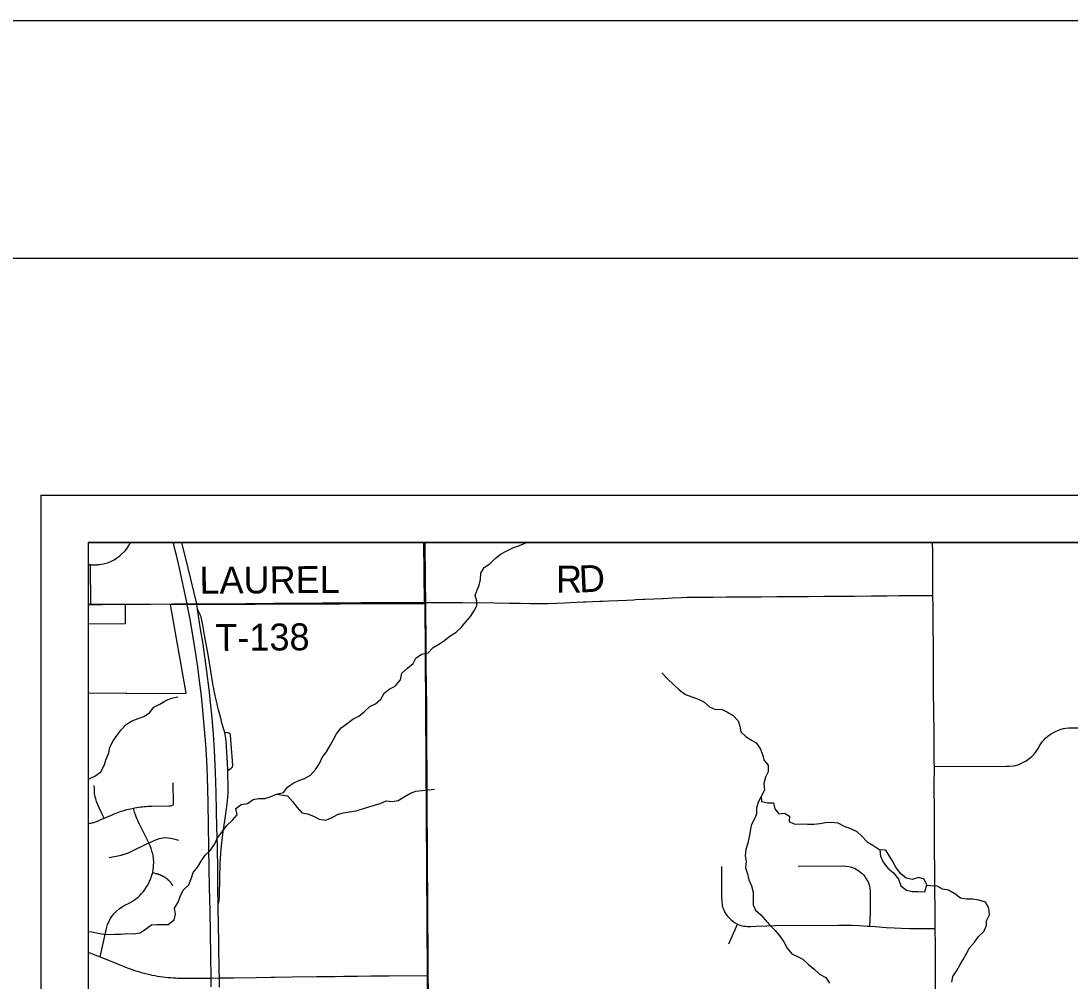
# Model space of a CAD drawing. Extents: x 0 to 34, y 0 to 22.
# Drawn here: x 1.958 to 4.171, y 19.975 to 22 of the extents above; entities that cross this region are included whole.
import ezdxf

# ---------------------------------------------------------------- set-up
doc = ezdxf.new("R2010")
doc.units = 0
for name, color, linetype in [('GM_X_City_Street', 7, 'Continuous'), ('GM_X_Corporation', 7, 'Continuous'), ('GM_X_County_Road', 7, 'Continuous'), ('GM_X_Interchange_Ramps', 7, 'Continuous'), ('GM_X_Interstate_Route', 7, 'Continuous'), ('GM_X_Minor_Lake', 7, 'Continuous'), ('GM_X_Minor_River', 7, 'Continuous'), ('GM_X_Township_Road', 7, 'Continuous'), ('GM_X_Township_Road_Text', 7, 'Continuous'), ('SH_Border', 7, 'Continuous'), ('SH_Cut_Line', 7, 'Continuous'), ('SH_Data', 7, 'Continuous')]:
    doc.layers.add(name, color=color, linetype=linetype)

msp = doc.modelspace()

# ---------------------------------------------------------------- linework, layer by layer
at = {"layer": 'GM_X_City_Street'}
for points in [[(2.1049, 20.8529), (2.1165, 20.8532), (2.118, 20.8533), (2.1195, 20.8534), (2.1209, 20.8535), (2.1242, 20.8539), (2.1315, 20.855), (2.1409, 20.8574), (2.1479, 20.8603), (2.1545, 20.8637), (2.1607, 20.8675), (2.1667, 20.8718), (2.1706, 20.8755), (2.1771, 20.8822), (2.1813, 20.8871), (2.1857, 20.8935), (2.1891, 20.9)], [(2.1058, 20.7696), (2.1049, 20.8529), (2.1, 20.8529)]]:
    msp.add_lwpolyline(points, dxfattribs=at)
at = {"layer": 'GM_X_Corporation'}
msp.add_lwpolyline([(7.991, 17.7727), (7.9901, 18.1613), (7.988, 19.001), (7.9884, 19.0254), (7.9898, 19.1149), (7.9901, 19.6615), (7.9904, 20.2824), (7.9906, 20.6512), (7.9922, 20.9), (2.1, 20.9), (2.1, 14.1)], dxfattribs=at)
for points in [[(2.8077, 20.9), (2.1, 20.9), (2.1, 20.77), (2.1778, 20.7703), (2.1782, 20.7286), (2.1, 20.7282), (2.1, 20.5821), (2.1799, 20.5828), (2.1799, 20.5819), (2.3067, 20.5825), (2.2736, 20.7693), (2.8091, 20.7716)], [(2.8099, 20.9), (2.1, 20.9), (2.1, 19.0167), (2.421, 19.0236), (2.4288, 19.0238), (2.4392, 19.024), (2.8247, 19.0323), (2.8158, 19.9868), (2.8107, 20.774)], [(7.9922, 20.9), (2.8099, 20.9), (2.8107, 20.774), (2.8158, 19.9868), (2.8247, 19.0323), (3.279, 19.0395), (3.3208, 19.0402), (3.8964, 19.0508), (4.1999, 19.0575), (4.5008, 19.0629), (4.7704, 19.0672), (4.9094, 19.0728), (5.4081, 19.0763), (6.7986, 19.0964), (7.9898, 19.1149), (7.9901, 19.6615), (7.9904, 20.2824), (7.9906, 20.6512)]]:
    msp.add_lwpolyline(points, close=True, dxfattribs=at)
at = {"layer": 'GM_X_County_Road'}
for points in [[(2.8123, 20.7736), (2.8116, 20.8163), (2.8114, 20.8343), (2.8107, 20.8878), (2.8106, 20.9)], [(2.8185, 19.9221), (2.8174, 19.9871), (2.8171, 20.0205), (2.8168, 20.0629), (2.8167, 20.0878), (2.8166, 20.1044), (2.8165, 20.1166), (2.8162, 20.1612), (2.8161, 20.1727), (2.8159, 20.1965), (2.8157, 20.2197), (2.8156, 20.231), (2.8157, 20.271), (2.8153, 20.3258), (2.8149, 20.3639), (2.8148, 20.4016), (2.8147, 20.4326), (2.8146, 20.4531), (2.8145, 20.4695), (2.8142, 20.5109), (2.8141, 20.5363), (2.814, 20.5513), (2.8136, 20.5994), (2.8132, 20.6382), (2.8129, 20.6853), (2.8128, 20.7144), (2.8125, 20.7374), (2.8125, 20.7518), (2.8123, 20.7736)], [(2.1, 20.0362), (2.1142, 20.0305), (2.1256, 20.0264), (2.1622, 20.0116), (2.1822, 20.0035), (2.1874, 20.0015), (2.1899, 20.0006), (2.1926, 19.9996), (2.1975, 19.9979), (2.1979, 19.9978), (2.2031, 19.9961), (2.2084, 19.9945), (2.2138, 19.993), (2.2141, 19.9929), (2.2191, 19.9916), (2.2245, 19.9902), (2.2299, 19.989), (2.2325, 19.9885), (2.2353, 19.9879), (2.2408, 19.9868), (2.2462, 19.9859), (2.2512, 19.9851), (2.2517, 19.985), (2.2572, 19.9843), (2.2627, 19.9836), (2.2682, 19.983), (2.2737, 19.9826), (2.2793, 19.9822), (2.283, 19.982), (2.2848, 19.9819), (2.2891, 19.9817), (2.2995, 19.9816), (2.33, 19.9812), (2.3594, 19.9817), (2.3769, 19.9819), (2.3882, 19.982)], [(2.3882, 19.982), (2.3954, 19.9821), (2.4073, 19.9822), (2.4548, 19.9829), (2.4853, 19.9833), (2.4928, 19.9834), (2.5299, 19.9839), (2.5824, 19.9846), (2.6106, 19.9849), (2.6203, 19.985), (2.6393, 19.9853), (2.6495, 19.9854), (2.6678, 19.9857), (2.6961, 19.986), (2.704, 19.9862), (2.7148, 19.9863), (2.7339, 19.9866), (2.8174, 19.9871)]]:
    msp.add_lwpolyline(points, dxfattribs=at)
at = {"layer": 'GM_X_Interchange_Ramps'}
for points in [[(2.3743, 20.135), (2.3757, 20.1409), (2.3765, 20.1455), (2.3771, 20.1572), (2.3784, 20.2242), (2.3804, 20.2539), (2.3843, 20.2851), (2.3891, 20.3178), (2.3923, 20.3433), (2.3944, 20.3621), (2.3952, 20.3754), (2.3956, 20.3917), (2.3947, 20.4089), (2.3943, 20.4196), (2.3937, 20.4345), (2.3907, 20.4821), (2.3903, 20.4871), (2.3898, 20.4912), (2.3891, 20.4949), (2.3882, 20.4992), (2.3862, 20.5057), (2.3835, 20.5149), (2.3814, 20.5222), (2.3802, 20.5268), (2.3776, 20.5373), (2.3751, 20.5472), (2.3736, 20.5531), (2.3718, 20.5601), (2.37, 20.5683), (2.368, 20.577), (2.3665, 20.5844), (2.3658, 20.5875), (2.3648, 20.5923), (2.3638, 20.5978), (2.363, 20.602), (2.3586, 20.629), (2.3528, 20.6638), (2.3457, 20.705), (2.3419, 20.7256), (2.3382, 20.7434), (2.3371, 20.7465), (2.3355, 20.7498), (2.3307, 20.7596)], [(2.3943, 20.4196), (2.4016, 20.4244), (2.4031, 20.4255), (2.4041, 20.4267), (2.4046, 20.4279), (2.4049, 20.4297), (2.4036, 20.4486), (2.4023, 20.4656), (2.4008, 20.4846), (2.4002, 20.4941), (2.4, 20.4954), (2.3995, 20.4966), (2.3986, 20.4974), (2.3977, 20.4979), (2.3965, 20.4983), (2.3945, 20.4985), (2.3882, 20.4992)]]:
    msp.add_lwpolyline(points, dxfattribs=at)
at = {"layer": 'GM_X_Interstate_Route'}
for points in [[(2.3088, 20.7697), (2.3086, 20.7707), (2.2912, 20.8525), (2.2883, 20.8646), (2.286, 20.8738), (2.2838, 20.883), (2.2806, 20.8959), (2.2795, 20.9)], [(2.329, 20.7708), (2.3108, 20.8461), (2.2974, 20.9)], [(2.3597, 19.9628), (2.3594, 19.9817), (2.357, 20.1241), (2.3562, 20.1722), (2.3553, 20.2126), (2.3544, 20.2567), (2.3539, 20.3031), (2.3532, 20.3522), (2.3514, 20.4059), (2.35, 20.4413), (2.3479, 20.4739), (2.3448, 20.5139), (2.3417, 20.5463), (2.3389, 20.5765), (2.335, 20.6082), (2.3311, 20.6377), (2.3245, 20.6828), (2.3152, 20.7382), (2.3088, 20.7697)], [(2.3773, 19.9621), (2.3769, 19.9819), (2.3763, 19.999), (2.3759, 20.0507), (2.3749, 20.0994), (2.3745, 20.1253), (2.3743, 20.135), (2.3737, 20.1693), (2.3732, 20.2102), (2.3728, 20.2568), (2.3713, 20.3002), (2.371, 20.3333), (2.37, 20.3729), (2.3689, 20.4151), (2.3665, 20.4623), (2.3643, 20.4961), (2.3613, 20.5298), (2.3583, 20.5629), (2.3552, 20.59), (2.3505, 20.6279), (2.3424, 20.6858), (2.3372, 20.7177), (2.3307, 20.7596), (2.329, 20.7708)]]:
    msp.add_lwpolyline(points, dxfattribs=at)
at = {"layer": 'GM_X_Minor_Lake'}
for points in [[(3.7698, 20.2527), (3.7708, 20.2386), (3.7767, 20.2258), (3.7863, 20.2131), (3.7982, 20.2034), (3.8091, 20.1899), (3.8142, 20.1764), (3.8257, 20.1671), (3.8379, 20.1643), (3.8508, 20.1641), (3.8644, 20.1636)], [(3.7699, 20.2523), (3.7708, 20.2386), (3.7767, 20.2258), (3.7863, 20.2131), (3.7982, 20.2034), (3.8091, 20.1899), (3.8142, 20.1764), (3.8257, 20.1671), (3.8379, 20.1643), (3.8508, 20.1641), (3.8644, 20.1636)], [(3.8644, 20.1636), (3.8687, 20.1781), (3.8635, 20.1905), (3.851, 20.1937), (3.8382, 20.1893), (3.8249, 20.1921), (3.813, 20.2022), (3.8037, 20.2153), (3.7974, 20.2277), (3.7904, 20.239), (3.7823, 20.2513), (3.7699, 20.2523)], [(3.8644, 20.1636), (3.8687, 20.1781), (3.8635, 20.1905), (3.851, 20.1937), (3.8382, 20.1893), (3.8249, 20.1921), (3.813, 20.2022), (3.8037, 20.2153), (3.7974, 20.2277), (3.7904, 20.239), (3.7823, 20.2513), (3.7701, 20.2523)]]:
    msp.add_lwpolyline(points, dxfattribs=at)
at = {"layer": 'GM_X_Minor_River'}
for points in [[(2.4971, 20.3693), (2.5121, 20.3729), (2.5206, 20.3845), (2.5326, 20.3923), (2.5442, 20.3982), (2.5566, 20.4026), (2.5686, 20.4096), (2.5798, 20.4216), (2.5882, 20.4338), (2.5933, 20.4465), (2.6026, 20.4588), (2.6107, 20.4718), (2.6176, 20.4844), (2.6238, 20.4967), (2.6334, 20.509), (2.6461, 20.5187), (2.6585, 20.5273), (2.6708, 20.534), (2.6824, 20.5433), (2.6943, 20.5545), (2.7063, 20.56), (2.7175, 20.5701), (2.7241, 20.5827), (2.7345, 20.5909), (2.7476, 20.5975), (2.7584, 20.6106), (2.7612, 20.6243), (2.7738, 20.6352), (2.7854, 20.6449), (2.7913, 20.6564), (2.8032, 20.6645), (2.8168, 20.6678), (2.8279, 20.6786), (2.8407, 20.6864), (2.8522, 20.6942), (2.8634, 20.7032), (2.8758, 20.711), (2.8866, 20.721), (2.8962, 20.7326), (2.9066, 20.7438), (2.9151, 20.7572), (2.9194, 20.7668), (2.9197, 20.7763), (2.9164, 20.7883), (2.92, 20.7979), (2.9247, 20.8101), (2.9272, 20.8223), (2.9284, 20.8352), (2.9354, 20.8475), (2.9474, 20.8549), (2.9585, 20.8665), (2.9697, 20.8754), (2.9828, 20.8829), (2.996, 20.8888), (3.0095, 20.8936), (3.0219, 20.8991), (3.0245, 20.9)], [(3.31, 20.6252), (3.3228, 20.6122), (3.3347, 20.601), (3.3462, 20.5894), (3.36, 20.5794), (3.373, 20.5747), (3.3851, 20.5704), (3.3985, 20.5641), (3.4104, 20.5534), (3.423, 20.5483), (3.4358, 20.5489), (3.4484, 20.5423), (3.4607, 20.5356), (3.4711, 20.5244), (3.4743, 20.5127), (3.4764, 20.5006), (3.4875, 20.4906), (3.499, 20.4836), (3.5086, 20.478), (3.5171, 20.4657), (3.5219, 20.4528), (3.5259, 20.4404), (3.534, 20.4303), (3.5339, 20.4166), (3.5288, 20.4051), (3.5252, 20.3918), (3.5262, 20.3782), (3.5193, 20.3644)], [(2.1, 20.4013), (2.102, 20.4018), (2.1143, 20.4077), (2.127, 20.4167), (2.134, 20.4297), (2.1383, 20.4434), (2.1437, 20.4564), (2.1458, 20.4686), (2.1528, 20.4816), (2.1609, 20.4939), (2.1694, 20.5054), (2.1805, 20.517), (2.1929, 20.5244), (2.2053, 20.5288), (2.2173, 20.5332), (2.2296, 20.541), (2.2385, 20.5526), (2.2513, 20.5592), (2.264, 20.5667), (2.276, 20.5718), (2.2892, 20.5747)], [(2.4971, 20.3693), (2.5202, 20.3662), (2.531, 20.3539), (2.5411, 20.3416), (2.5503, 20.3303), (2.5625, 20.3279), (2.5751, 20.3232), (2.5873, 20.3166), (2.6002, 20.3145), (2.613, 20.3193), (2.6257, 20.3263), (2.6381, 20.3304), (2.6513, 20.3321), (2.6649, 20.3342), (2.6784, 20.3387), (2.6901, 20.3419), (2.7036, 20.3463), (2.7161, 20.3499), (2.7284, 20.3555), (2.7413, 20.3538), (2.7538, 20.3559), (2.7665, 20.3637), (2.7796, 20.3715), (2.7913, 20.3755), (2.8045, 20.3773), (2.8173, 20.3783), (2.8302, 20.38)], [(2.1, 20.0795), (2.1076, 20.079), (2.1209, 20.0765), (2.1327, 20.0745), (2.1425, 20.0735), (2.1558, 20.0741), (2.169, 20.0743), (2.1826, 20.0753), (2.1955, 20.0748), (2.2094, 20.0773), (2.2206, 20.0844), (2.2333, 20.0937), (2.2451, 20.0946), (2.2572, 20.0945), (2.2689, 20.0947), (2.2816, 20.1044), (2.2844, 20.1162), (2.2819, 20.1291), (2.2896, 20.1417), (2.294, 20.1536), (2.3005, 20.167), (2.3121, 20.1782), (2.3171, 20.1912), (2.3211, 20.2041), (2.3311, 20.2165), (2.338, 20.228), (2.3469, 20.241), (2.3577, 20.2514), (2.3669, 20.2649), (2.3727, 20.2771), (2.3823, 20.2898), (2.3927, 20.3037), (2.4042, 20.3145), (2.4142, 20.3257), (2.4117, 20.3393), (2.4226, 20.3478), (2.4361, 20.35), (2.4477, 20.3585), (2.4594, 20.3602), (2.4723, 20.3605), (2.4839, 20.3637), (2.4971, 20.3693)], [(3.5193, 20.3644), (3.5138, 20.3537), (3.5095, 20.3407), (3.5093, 20.327), (3.505, 20.3174), (3.4984, 20.304), (3.496, 20.2915), (3.4939, 20.2793), (3.4915, 20.266), (3.4868, 20.253), (3.4859, 20.2397), (3.4876, 20.2276), (3.4867, 20.2139), (3.4907, 20.2011), (3.4936, 20.1886), (3.4988, 20.1758), (3.5024, 20.163), (3.5026, 20.1501), (3.5025, 20.1364), (3.5076, 20.1251), (3.5187, 20.1147), (3.5276, 20.1046), (3.5377, 20.093), (3.5488, 20.0822), (3.5585, 20.0702), (3.5674, 20.0578), (3.5744, 20.0447), (3.5841, 20.0327), (3.5975, 20.0265), (3.607, 20.0217), (3.6189, 20.0105), (3.6312, 20.0001), (3.6427, 19.9897), (3.6561, 19.9827), (3.6635, 19.9707)], [(3.5193, 20.3644), (3.5198, 20.3538), (3.5327, 20.3513), (3.5452, 20.3515), (3.5485, 20.3383), (3.5566, 20.3282), (3.5683, 20.3296), (3.579, 20.3233), (3.5785, 20.3115), (3.5906, 20.3064), (3.6043, 20.307), (3.6168, 20.3061), (3.6307, 20.3064), (3.6428, 20.3077), (3.6553, 20.3098), (3.6681, 20.3101), (3.6814, 20.3091), (3.6947, 20.3022), (3.7081, 20.2967), (3.721, 20.2909), (3.7322, 20.2801), (3.743, 20.2692), (3.7552, 20.2619), (3.7698, 20.252)], [(3.9218, 19.9733), (3.9235, 19.9851), (3.9324, 19.9974), (3.9386, 20.0089), (3.9452, 20.0208), (3.9522, 20.0331), (3.9588, 20.0453), (3.9703, 20.0577), (3.9776, 20.0696), (3.9888, 20.08), (3.9946, 20.0923), (3.9945, 20.1021), (4.001, 20.1151), (3.9997, 20.1288), (3.9926, 20.1415), (3.9786, 20.1459), (3.966, 20.1479), (3.9524, 20.1477), (3.9399, 20.1501), (3.928, 20.159), (3.9143, 20.1671), (3.9017, 20.1692), (3.8903, 20.1754), (3.8766, 20.1759), (3.8682, 20.1766)]]:
    msp.add_lwpolyline(points, dxfattribs=at)
at = {"layer": 'GM_X_Township_Road'}
for p, q in [((2.178, 20.7699), (2.181, 20.77)), ((3.451, 20.0536), (3.4696, 20.0952))]:
    msp.add_line(p, q, dxfattribs=at)
for points in [[(3.8854, 20.2161), (3.8853, 20.2435), (3.885, 20.3202), (3.8848, 20.3349), (3.8846, 20.3853), (3.8847, 20.4275), (3.8846, 20.4364), (3.8844, 20.4602), (3.8841, 20.4891), (3.884, 20.4975), (3.8836, 20.5459), (3.8834, 20.5514), (3.8832, 20.5776), (3.8831, 20.6304), (3.8828, 20.6655), (3.8826, 20.6915), (3.8825, 20.7135), (3.8822, 20.7414), (3.8821, 20.7647), (3.8815, 20.7886), (3.8814, 20.8121), (3.8813, 20.8454), (3.8812, 20.8796), (3.8811, 20.9)], [(2.8123, 20.7736), (2.8889, 20.7733), (2.9569, 20.7726), (2.9881, 20.7722), (2.9946, 20.7722), (3.0116, 20.772), (3.0325, 20.7718), (3.0593, 20.7715), (3.0704, 20.7714), (3.0881, 20.7722), (3.1048, 20.7729), (3.1159, 20.7734), (3.1445, 20.7747), (3.1499, 20.775), (3.1794, 20.7763), (3.1846, 20.7766), (3.1982, 20.7772), (3.2171, 20.778), (3.2361, 20.7789), (3.251, 20.7796), (3.2544, 20.7797), (3.271, 20.7805), (3.2737, 20.7806), (3.2927, 20.7815), (3.3106, 20.7823), (3.3124, 20.7823), (3.3323, 20.7832), (3.3512, 20.7841), (3.3633, 20.7847), (3.3856, 20.7848), (3.4185, 20.7851), (3.4457, 20.7853), (3.479, 20.7855), (3.5195, 20.7858), (3.5523, 20.7861), (3.586, 20.7863), (3.6189, 20.7866), (3.6522, 20.7868), (3.6685, 20.787), (3.6854, 20.7871), (3.7159, 20.7873), (3.752, 20.7876), (3.7633, 20.7877), (3.785, 20.7879), (3.8106, 20.7881), (3.8815, 20.7886)], [(2.1, 20.7695), (2.1058, 20.7696), (2.1294, 20.7697), (2.1463, 20.7698), (2.1621, 20.7698), (2.175, 20.7699), (2.178, 20.7699)], [(2.181, 20.77), (2.1938, 20.77), (2.212, 20.7701), (2.2317, 20.7702), (2.2784, 20.7706)], [(2.2784, 20.7706), (2.3086, 20.7707), (2.329, 20.7708), (2.3558, 20.7709), (2.3694, 20.771), (2.3874, 20.7711), (2.4328, 20.7716), (2.4417, 20.7716)], [(2.4417, 20.7716), (2.4536, 20.7717), (2.4742, 20.7718), (2.4913, 20.772), (2.5157, 20.7721), (2.5421, 20.7723), (2.571, 20.7725), (2.5938, 20.7727), (2.6183, 20.7728), (2.6419, 20.773), (2.6761, 20.7733), (2.6932, 20.7734), (2.7071, 20.7735), (2.7308, 20.7736), (2.7741, 20.7739), (2.8123, 20.7736)], [(3.8847, 20.4275), (4.0369, 20.4284), (4.0426, 20.4285), (4.0509, 20.4292), (4.0556, 20.4302), (4.0608, 20.4316), (4.0658, 20.4335), (4.0713, 20.436), (4.0781, 20.44), (4.0841, 20.4439), (4.0902, 20.4489), (4.0944, 20.4533), (4.0979, 20.4576), (4.1009, 20.4616), (4.1047, 20.4677), (4.1066, 20.4714), (4.1092, 20.4754), (4.1124, 20.4796), (4.1157, 20.4836), (4.1193, 20.4875), (4.1237, 20.4915), (4.1268, 20.4939), (4.1308, 20.4967), (4.1358, 20.4996), (4.1399, 20.5017), (4.1468, 20.5047), (4.1522, 20.5064), (4.1573, 20.5077), (4.1622, 20.5086), (4.1685, 20.5091), (4.2109, 20.5094)], [(2.1338, 20.3189), (2.1289, 20.3288), (2.1234, 20.3405), (2.1177, 20.354), (2.1159, 20.3594), (2.1147, 20.3636), (2.1138, 20.3677), (2.1135, 20.3708), (2.1133, 20.3733), (2.113, 20.3805), (2.1128, 20.3879)], [(2.2781, 20.3461), (2.2791, 20.347), (2.2799, 20.3486), (2.2802, 20.3504), (2.2795, 20.3934)], [(2.1, 20.307), (2.1005, 20.3071), (2.1025, 20.3075), (2.1044, 20.308), (2.1064, 20.3084), (2.1083, 20.3089), (2.1102, 20.3094), (2.112, 20.31), (2.1139, 20.3106), (2.1158, 20.3112), (2.1176, 20.3118), (2.1195, 20.3125), (2.1213, 20.3133), (2.1242, 20.3145), (2.1338, 20.3189), (2.1495, 20.3255), (2.155, 20.3279), (2.1587, 20.3293), (2.1624, 20.3307), (2.1661, 20.3321), (2.1699, 20.3333), (2.1737, 20.3346), (2.1775, 20.3357), (2.1813, 20.3368), (2.185, 20.3376), (2.189, 20.3385), (2.1953, 20.3399), (2.1987, 20.3406), (2.2029, 20.3414), (2.2069, 20.342), (2.2108, 20.3425), (2.2147, 20.343), (2.2187, 20.3434), (2.2226, 20.3437), (2.2266, 20.3439), (2.2306, 20.3441), (2.2345, 20.3442), (2.271, 20.3447), (2.2728, 20.3446), (2.2745, 20.3448), (2.2764, 20.3452), (2.2781, 20.3461)], [(2.1256, 20.0264), (2.1388, 20.0864), (2.141, 20.0948), (2.1426, 20.0984), (2.1448, 20.1033), (2.1472, 20.1078), (2.1496, 20.1111), (2.1519, 20.1143), (2.1544, 20.1173), (2.159, 20.122), (2.1657, 20.1276), (2.1727, 20.1323), (2.1788, 20.1358), (2.1852, 20.1392), (2.1916, 20.1427), (2.198, 20.1467), (2.2052, 20.1523), (2.2089, 20.1559), (2.2125, 20.1597), (2.2159, 20.1638), (2.2186, 20.1673), (2.223, 20.1738), (2.2249, 20.1769), (2.2277, 20.1815), (2.2297, 20.1858), (2.2313, 20.1895), (2.2339, 20.1964), (2.2364, 20.2043), (2.2372, 20.2106), (2.2378, 20.2155), (2.238, 20.2199), (2.2382, 20.2243), (2.2378, 20.2344), (2.2371, 20.2392), (2.2362, 20.2436), (2.2346, 20.2495), (2.2327, 20.2552), (2.2308, 20.2605), (2.2279, 20.267), (2.2095, 20.3031), (2.207, 20.3083), (2.2044, 20.3141), (2.2027, 20.3179), (2.2012, 20.3219), (2.1996, 20.3259), (2.1978, 20.3312), (2.1953, 20.3399)], [(2.1443, 20.2357), (2.1693, 20.2411), (2.1709, 20.2414), (2.1725, 20.2418), (2.1741, 20.2422), (2.1757, 20.2427), (2.1773, 20.2431), (2.1788, 20.2436), (2.1804, 20.2441), (2.1819, 20.2447), (2.1835, 20.2453), (2.185, 20.2459), (2.1865, 20.2465), (2.188, 20.2472), (2.1894, 20.2479), (2.1919, 20.2491), (2.2279, 20.267)], [(2.2279, 20.267), (2.2361, 20.2706), (2.244, 20.2738), (2.2504, 20.276), (2.2538, 20.2768), (2.2576, 20.2776), (2.2612, 20.2779), (2.2697, 20.2775), (2.2738, 20.2768), (2.2809, 20.2752), (2.2905, 20.2723)], [(2.2364, 20.2043), (2.243, 20.2022), (2.2443, 20.2018), (2.2451, 20.2016), (2.2459, 20.2014), (2.2467, 20.2012), (2.2475, 20.2009), (2.2483, 20.2007), (2.2491, 20.2004), (2.2499, 20.2001), (2.2507, 20.1998), (2.2515, 20.1995), (2.2523, 20.1992), (2.2531, 20.1989), (2.2538, 20.1985), (2.2546, 20.1982), (2.2554, 20.1978), (2.2562, 20.1974), (2.2569, 20.197), (2.2577, 20.1966), (2.2585, 20.1962), (2.2592, 20.1957), (2.26, 20.1953), (2.2607, 20.1948), (2.2615, 20.1944), (2.2622, 20.1939), (2.2629, 20.1934), (2.2636, 20.1929), (2.2643, 20.1924), (2.265, 20.1918), (2.2657, 20.1913), (2.2664, 20.1907), (2.267, 20.1902), (2.2677, 20.1896), (2.2683, 20.189), (2.269, 20.1884), (2.2696, 20.1878), (2.2702, 20.1872), (2.2708, 20.1866), (2.2714, 20.186), (2.2723, 20.185), (2.2728, 20.1843), (2.2733, 20.1837), (2.2738, 20.183), (2.2743, 20.1823), (2.2748, 20.1817), (2.2753, 20.181), (2.2757, 20.1803), (2.2762, 20.1796), (2.2766, 20.1789), (2.277, 20.1782), (2.2774, 20.1775), (2.2782, 20.176)], [(3.4357, 20.2172), (3.436, 20.1496), (3.4362, 20.1446), (3.4364, 20.1414), (3.4368, 20.1375), (3.4374, 20.1346), (3.4381, 20.1314), (3.4397, 20.1267), (3.4423, 20.1215), (3.4459, 20.1154), (3.4482, 20.1123), (3.4509, 20.109), (3.453, 20.1069), (3.4554, 20.1048), (3.4609, 20.1004), (3.4649, 20.0978), (3.4696, 20.0952), (3.4764, 20.0928), (3.479, 20.0921), (3.4831, 20.0911), (3.4868, 20.0908), (3.4902, 20.0905), (3.4977, 20.0907), (3.5079, 20.091), (3.5317, 20.0919), (3.5494, 20.0923), (3.6824, 20.0931), (3.7102, 20.0929), (3.7266, 20.0923), (3.7429, 20.0914), (3.748, 20.0911), (3.7607, 20.0903), (3.7832, 20.0886), (3.7997, 20.0877), (3.8149, 20.0868), (3.8333, 20.0861), (3.882, 20.0862), (3.8867, 20.0863)], [(3.5971, 20.2176), (3.6929, 20.2181), (3.6985, 20.2177), (3.7046, 20.2169), (3.7098, 20.2156), (3.7136, 20.2143), (3.7178, 20.2125), (3.7206, 20.2109), (3.7233, 20.2092), (3.7295, 20.2045), (3.7324, 20.2018), (3.7351, 20.1991), (3.738, 20.1956), (3.7409, 20.1911), (3.7431, 20.1875), (3.7448, 20.1843), (3.7464, 20.1805), (3.7477, 20.1757), (3.7485, 20.1712), (3.749, 20.1673), (3.7494, 20.161), (3.7495, 20.1557), (3.7492, 20.1185), (3.748, 20.0911)], [(3.8903, 19.4814), (3.8899, 19.5378), (3.8897, 19.5614), (3.8894, 19.5851), (3.8893, 19.6264), (3.8892, 19.6493), (3.889, 19.7375), (3.8882, 19.8115), (3.8877, 19.875), (3.8875, 19.9329), (3.8874, 19.9648), (3.8873, 19.9785), (3.8871, 20.0349), (3.887, 20.0509), (3.8867, 20.0863), (3.8863, 20.1111), (3.8861, 20.1353), (3.886, 20.1585), (3.8858, 20.1728), (3.8855, 20.206), (3.8854, 20.2161)]]:
    msp.add_lwpolyline(points, dxfattribs=at)
at = {"layer": 'SH_Border'}
msp.add_lwpolyline([(1.5, 21.5), (33.5, 21.5), (33.5, 0.5), (1.5, 0.5)], close=True, dxfattribs=at)
at = {"layer": 'SH_Cut_Line'}
msp.add_lwpolyline([(0, 0), (34, 0), (34, 22), (0, 22)], close=True, dxfattribs=at)
at = {"layer": 'SH_Data'}
for p, q in [((2, 21), (9, 21)), ((2, 21), (2, 14)), ((2.1, 20.9), (2.1, 14.1)), ((2.1, 20.9), (8.9, 20.9))]:
    msp.add_line(p, q, dxfattribs=at)

# ---------------------------------------------------------------- texts
at = {"layer": 'GM_X_Township_Road_Text'}
for s, height, rotation, p in [('LAUREL', 0.05682, 0.3481, (2.335, 20.7921)), ('R', 0.0568, 359.961, (3.0867, 20.7946)), ('D', 0.0568, 2.7351, (3.1364, 20.7946)), ('T-138', 0.05682, 0.5614, (2.3686, 20.6711))]:
    msp.add_text(s, height=height, rotation=rotation, dxfattribs=at).set_placement(p)

doc.saveas('drawing.dxf')
